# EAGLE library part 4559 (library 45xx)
8-bit SUCCESSIVE APPROXIMATION REGISTER
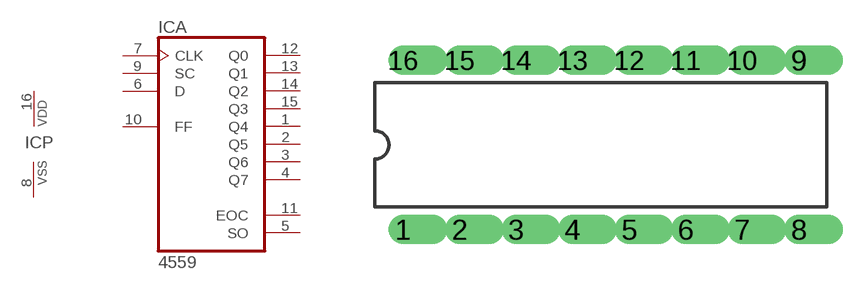
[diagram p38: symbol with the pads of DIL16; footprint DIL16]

Designator prefix IC; gates A=4559 P=PWRN

## 4559N  [DIL16]
1  A:Q4  out
2  A:Q5  out
3  A:Q6  out
4  A:Q7  out
5  A:SO  out
6  A:D  in
7  A:CLK  in
8  P:VSS  pwr
9  A:SC  in
10  A:FF  in
11  A:EOC  out
12  A:Q0  out
13  A:Q1  out
14  A:Q2  out
15  A:Q3  out
16  P:VDD  pwr

## Footprint DIL16 (pad centres in mm)
Dual In Line
drill 0.813 offset: 1 -8.89,-3.81; 2 -6.35,-3.81; 3 -3.81,-3.81; 4 -1.27,-3.81; 5 1.27,-3.81; 6 3.81,-3.81; 7 6.35,-3.81; 8 8.89,-3.81; 9 8.89,3.81; 10 6.35,3.81; 11 3.81,3.81; 12 1.27,3.81; 13 -1.27,3.81; 14 -3.81,3.81; 15 -6.35,3.81; 16 -8.89,3.81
